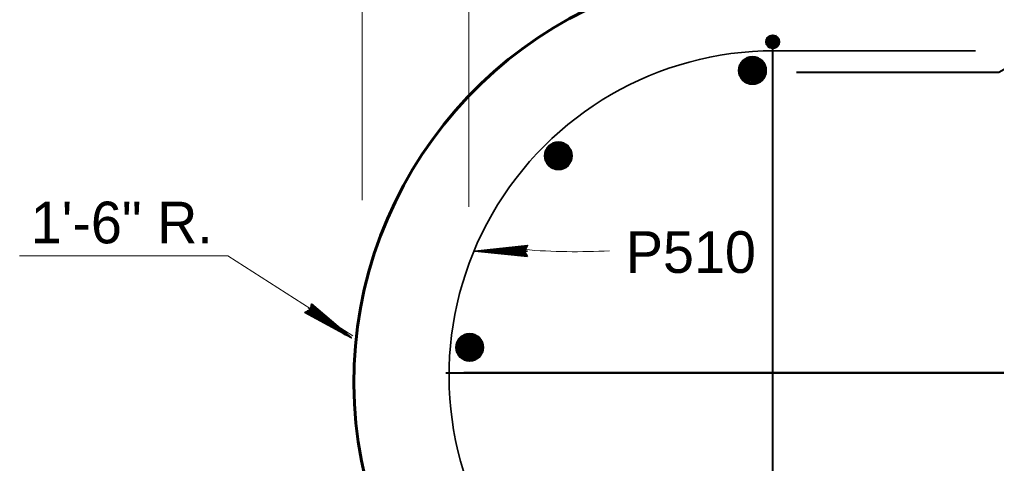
# Model space of a CAD drawing. Extents: x 14.14 to 17.34, y -1.61 to 0.38.
# Drawn here: x 14.4549 to 14.6504, y -0.5088 to -0.42 of the extents above; entities that cross this region are included whole.
import ezdxf

# ---------------------------------------------------------------- set-up
doc = ezdxf.new("R2010")
doc.units = 0
doc.header["$LTSCALE"] = 0.0033
doc.layers.add('1', color=7, linetype='Continuous', lineweight=40)

msp = doc.modelspace()

# ---------------------------------------------------------------- linework, layer by layer
at = {"layer": '1', "lineweight": 13}
for p, q in [((14.5235, -0.456083), (14.5235, -0.32)), ((14.544833, -0.457417), (14.544833, -0.3515))]:
    msp.add_line(p, q, dxfattribs=at)
at = {"layer": '1'}
for p, q in [((14.605, -0.425583), (14.604667, -0.423583)), ((14.605083, -0.4255), (14.60475, -0.423583)), ((14.606333, -0.42325), (14.604833, -0.423333)), ((14.606333, -0.423417), (14.604833, -0.4235)), ((14.606333, -0.4235), (14.604833, -0.423583)), ((14.606333, -0.423583), (14.604833, -0.423667)), ((14.605167, -0.4255), (14.604833, -0.423583)), ((14.606333, -0.423667), (14.604833, -0.42375)), ((14.606333, -0.42375), (14.604833, -0.423833)), ((14.606333, -0.423833), (14.604833, -0.423917)), ((14.606333, -0.423917), (14.604833, -0.424)), ((14.606333, -0.423917), (14.604833, -0.424)), ((14.606333, -0.424), (14.604833, -0.424167)), ((14.606333, -0.424167), (14.604833, -0.424333)), ((14.60525, -0.4255), (14.604917, -0.4235)), ((14.6055, -0.4255), (14.605083, -0.4235)), ((14.605667, -0.425417), (14.60525, -0.4235)), ((14.60575, -0.425417), (14.605333, -0.4235)), ((14.605833, -0.425417), (14.605417, -0.423417)), ((14.605917, -0.425417), (14.605583, -0.423417)), ((14.606, -0.425333), (14.605667, -0.423417)), ((14.606167, -0.425333), (14.60575, -0.423333)), ((14.60625, -0.425333), (14.605833, -0.423333)), ((14.606333, -0.425333), (14.606, -0.423333)), ((14.606417, -0.425333), (14.606083, -0.423333)), ((14.606583, -0.42525), (14.60625, -0.423333)), ((14.606417, -0.424333), (14.604917, -0.424417)), ((14.606417, -0.424417), (14.604917, -0.4245)), ((14.606417, -0.4245), (14.604917, -0.424583)), ((14.606417, -0.424583), (14.604917, -0.424667)), ((14.606417, -0.424667), (14.604917, -0.42475)), ((14.606417, -0.42475), (14.604917, -0.424833)), ((14.606417, -0.424833), (14.604917, -0.424917)), ((14.606417, -0.425), (14.604917, -0.425083)), ((14.606417, -0.425083), (14.604917, -0.425167)), ((14.606417, -0.425167), (14.604917, -0.42525)), ((14.606417, -0.42525), (14.604917, -0.425333)), ((14.606417, -0.425333), (14.604917, -0.425417)), ((14.605583, -0.425833), (14.605583, -0.557167)), ((14.601833, -0.429083), (14.603167, -0.428083)), ((14.603917, -0.428917), (14.602667, -0.42775)), ((14.5995, -0.428583), (14.604083, -0.43075)), ((14.599583, -0.43), (14.603417, -0.43075)), ((14.599667, -0.429583), (14.6035, -0.43025)), ((14.599667, -0.42975), (14.6035, -0.4305)), ((14.59975, -0.429), (14.603667, -0.42975)), ((14.59975, -0.429167), (14.603667, -0.429917)), ((14.59975, -0.429417), (14.603583, -0.430167)), ((14.599833, -0.428583), (14.60375, -0.42925)), ((14.599833, -0.42875), (14.60375, -0.4295)), ((14.599917, -0.42825), (14.60375, -0.428917)), ((14.599333, -0.431333), (14.603167, -0.432083)), ((14.599333, -0.4315), (14.603167, -0.43225)), ((14.599417, -0.430833), (14.603333, -0.431583)), ((14.599417, -0.431), (14.60325, -0.43175)), ((14.599417, -0.43125), (14.60325, -0.431917)), ((14.5995, -0.430417), (14.603417, -0.431167)), ((14.599583, -0.430167), (14.603417, -0.430917)), ((14.603667, -0.43175), (14.599917, -0.432167)), ((14.560667, -0.445667), (14.56525, -0.447833)), ((14.561, -0.445667), (14.564917, -0.446333)), ((14.561083, -0.445333), (14.564917, -0.446)), ((14.563, -0.446167), (14.564333, -0.445167)), ((14.565083, -0.446), (14.563833, -0.444833)), ((14.560667, -0.4475), (14.564583, -0.44825)), ((14.56075, -0.447083), (14.564583, -0.447833)), ((14.56075, -0.44725), (14.564583, -0.448)), ((14.560833, -0.446667), (14.564667, -0.447333)), ((14.560833, -0.446833), (14.564667, -0.447583)), ((14.560917, -0.446083), (14.564833, -0.446833)), ((14.560917, -0.44625), (14.564833, -0.447)), ((14.560917, -0.4465), (14.56475, -0.44725)), ((14.561, -0.445833), (14.564917, -0.446583)), ((14.5605, -0.448417), (14.564333, -0.449167)), ((14.5605, -0.448583), (14.564333, -0.449333)), ((14.560583, -0.447917), (14.5645, -0.448667)), ((14.560583, -0.448083), (14.564417, -0.448833)), ((14.560583, -0.448333), (14.564417, -0.449)), ((14.564833, -0.448833), (14.561083, -0.44925)), ((14.542917, -0.484), (14.5475, -0.486167)), ((14.543167, -0.484417), (14.547083, -0.485167)), ((14.543167, -0.484583), (14.547083, -0.485333)), ((14.543167, -0.484833), (14.547, -0.485583)), ((14.54325, -0.484), (14.547167, -0.484667)), ((14.54325, -0.484167), (14.547167, -0.484917)), ((14.543333, -0.483667), (14.547167, -0.484333)), ((14.54525, -0.4845), (14.546583, -0.4835)), ((14.547333, -0.484333), (14.546083, -0.483167)), ((14.54275, -0.48675), (14.546583, -0.4875)), ((14.542833, -0.48625), (14.54675, -0.487)), ((14.542833, -0.486417), (14.546667, -0.487167)), ((14.542833, -0.486667), (14.546667, -0.487333)), ((14.542917, -0.485833), (14.546833, -0.486583)), ((14.543, -0.485417), (14.546833, -0.486167)), ((14.543, -0.485583), (14.546833, -0.486333)), ((14.543083, -0.485), (14.546917, -0.485667)), ((14.543083, -0.485167), (14.546917, -0.485917)), ((14.54275, -0.486917), (14.546583, -0.487667)), ((14.547083, -0.487167), (14.543333, -0.487583)), ((14.54025, -0.490667), (14.964167, -0.490667))]:
    msp.add_line(p, q, dxfattribs=at)
at = {"layer": '1', "lineweight": 35}
for p, q in [((14.60525, -0.42625), (14.64625, -0.42625)), ((14.556333, -0.46525), (14.549, -0.466083)), ((14.556583, -0.466333), (14.546, -0.466333)), ((14.556333, -0.467167), (14.5485, -0.466167)), ((14.556333, -0.467167), (14.5485, -0.466333)), ((14.556333, -0.467333), (14.5485, -0.466417)), ((14.556333, -0.467333), (14.5485, -0.466417)), ((14.556333, -0.46725), (14.5485, -0.466417)), ((14.556333, -0.465417), (14.549, -0.466167)), ((14.556333, -0.4655), (14.549, -0.466333)), ((14.556417, -0.465667), (14.549083, -0.466417)), ((14.513417, -0.477), (14.519417, -0.482167)), ((14.5135, -0.477), (14.519417, -0.482167)), ((14.5135, -0.477), (14.519417, -0.482167)), ((14.51225, -0.478667), (14.51875, -0.482167)), ((14.512333, -0.4785), (14.518917, -0.482)), ((14.512417, -0.47825), (14.518917, -0.481917)), ((14.512417, -0.478583), (14.518833, -0.482167)), ((14.512667, -0.477583), (14.521333, -0.483667)), ((14.513333, -0.477083), (14.519333, -0.48225)), ((14.513333, -0.477083), (14.519167, -0.482417))]:
    msp.add_line(p, q, dxfattribs=at)
at = {"layer": '1', "lineweight": 60}
for p, q in [((14.59975, -0.428583), (14.599583, -0.4315)), ((14.6, -0.428583), (14.59975, -0.4315)), ((14.600167, -0.428583), (14.6, -0.431583)), ((14.600333, -0.428583), (14.600083, -0.431583)), ((14.6005, -0.428583), (14.600333, -0.431583)), ((14.60075, -0.428583), (14.600583, -0.431583)), ((14.601, -0.428583), (14.60075, -0.431583)), ((14.601083, -0.428667), (14.600917, -0.431583)), ((14.60125, -0.428667), (14.601083, -0.431583)), ((14.601417, -0.428667), (14.60125, -0.431583)), ((14.601667, -0.428667), (14.601417, -0.431583)), ((14.601833, -0.428667), (14.601667, -0.431583)), ((14.602083, -0.42875), (14.601833, -0.431667)), ((14.602333, -0.42875), (14.602083, -0.431667)), ((14.6025, -0.42875), (14.602333, -0.431667)), ((14.602583, -0.42875), (14.602417, -0.431667)), ((14.60275, -0.42875), (14.602583, -0.431667)), ((14.602833, -0.42875), (14.602667, -0.431667)), ((14.603083, -0.428833), (14.602833, -0.43175)), ((14.60325, -0.428833), (14.603083, -0.43175)), ((14.603417, -0.428833), (14.603167, -0.43175)), ((14.603583, -0.428833), (14.603417, -0.43175)), ((14.603833, -0.428833), (14.603667, -0.43175)), ((14.604083, -0.43075), (14.603917, -0.428917)), ((14.604083, -0.43075), (14.599333, -0.4315)), ((14.560917, -0.445667), (14.56075, -0.448583)), ((14.561167, -0.445667), (14.560917, -0.448583)), ((14.561333, -0.445667), (14.561167, -0.448667)), ((14.5615, -0.445667), (14.56125, -0.448667)), ((14.561667, -0.445667), (14.5615, -0.448667)), ((14.561917, -0.445667), (14.56175, -0.448667)), ((14.562167, -0.445667), (14.561917, -0.448667)), ((14.56225, -0.44575), (14.562083, -0.448667)), ((14.562417, -0.44575), (14.56225, -0.448667)), ((14.562583, -0.44575), (14.562417, -0.448667)), ((14.562833, -0.44575), (14.562583, -0.448667)), ((14.563, -0.44575), (14.562833, -0.448667)), ((14.56325, -0.445833), (14.563, -0.44875)), ((14.5635, -0.445833), (14.56325, -0.44875)), ((14.563667, -0.445833), (14.5635, -0.44875)), ((14.56375, -0.445833), (14.563583, -0.44875)), ((14.563917, -0.445833), (14.56375, -0.44875)), ((14.564, -0.445833), (14.563833, -0.44875)), ((14.56425, -0.445917), (14.564, -0.448833)), ((14.564417, -0.445917), (14.56425, -0.448833)), ((14.564583, -0.445917), (14.564333, -0.448833)), ((14.56475, -0.445917), (14.564583, -0.448833)), ((14.565, -0.445917), (14.564833, -0.448833)), ((14.56525, -0.447833), (14.565083, -0.446)), ((14.56525, -0.447833), (14.5605, -0.448583)), ((14.543167, -0.484), (14.543, -0.486917)), ((14.543417, -0.484), (14.543167, -0.486917)), ((14.543583, -0.484), (14.543417, -0.487)), ((14.54375, -0.484), (14.5435, -0.487)), ((14.543917, -0.484), (14.54375, -0.487)), ((14.544167, -0.484), (14.544, -0.487)), ((14.544417, -0.484), (14.544167, -0.487)), ((14.5445, -0.484083), (14.544333, -0.487)), ((14.544667, -0.484083), (14.5445, -0.487)), ((14.544833, -0.484083), (14.544667, -0.487)), ((14.545083, -0.484083), (14.544833, -0.487)), ((14.54525, -0.484083), (14.545083, -0.487)), ((14.5455, -0.484167), (14.54525, -0.487083)), ((14.54575, -0.484167), (14.5455, -0.487083)), ((14.545917, -0.484167), (14.54575, -0.487083)), ((14.546, -0.484167), (14.545833, -0.487083)), ((14.546167, -0.484167), (14.546, -0.487083)), ((14.54625, -0.484167), (14.546083, -0.487083)), ((14.5465, -0.48425), (14.54625, -0.487167)), ((14.546667, -0.48425), (14.5465, -0.487167)), ((14.546833, -0.48425), (14.546583, -0.487167)), ((14.547, -0.48425), (14.546833, -0.487167)), ((14.54725, -0.48425), (14.547083, -0.487167)), ((14.5475, -0.486167), (14.547333, -0.484333)), ((14.5475, -0.486167), (14.54275, -0.486917))]:
    msp.add_line(p, q, dxfattribs=at)
at = {"layer": '1'}
for points in [[(14.605583, -0.42575), (14.605917, -0.423167), (14.606417, -0.4255), (14.605333, -0.423167), (14.604917, -0.425583), (14.604583, -0.423583), (14.606667, -0.423583), (14.604333, -0.4245), (14.606917, -0.42425), (14.604583, -0.42525), (14.606917, -0.424917), (14.604333, -0.424083), (14.606083, -0.425667), (14.60625, -0.42325), (14.604417, -0.424917), (14.606833, -0.423833), (14.606417, -0.4255), (14.604917, -0.425583), (14.604333, -0.4245), (14.604583, -0.423583), (14.605333, -0.423167), (14.60625, -0.42325), (14.606833, -0.423833), (14.60575, -0.4245), (14.604833, -0.423333), (14.604583, -0.42525), (14.60575, -0.4245), (14.60625, -0.425583), (14.606917, -0.424583), (14.605833, -0.4245), (14.604583, -0.423667), (14.605833, -0.425667), (14.606167, -0.424333), (14.606667, -0.423583)], [(14.610417, -0.4305), (14.650917, -0.4305), (14.658167, -0.426333), (14.888, -0.426333)], [(14.599333, -0.4315), (14.601417, -0.43275), (14.603167, -0.43225), (14.604083, -0.43075)], [(14.5605, -0.448583), (14.562583, -0.449833), (14.564333, -0.449333), (14.56525, -0.447833)], [(14.54275, -0.486917), (14.544833, -0.488167), (14.546583, -0.487667), (14.5475, -0.486167)], [(14.74375, -0.490667), (14.665167, -0.490667), (14.543833, -0.490667)]]:
    msp.add_lwpolyline(points, dxfattribs=at)
at = {"layer": '1', "lineweight": 60}
for points in [[(14.603167, -0.43225), (14.603167, -0.428083), (14.6015, -0.43275), (14.602, -0.427583), (14.599917, -0.432167), (14.600667, -0.427667), (14.60225, -0.432667), (14.599083, -0.429333), (14.603917, -0.428917), (14.600667, -0.432583), (14.602667, -0.42775), (14.5995, -0.428583), (14.599333, -0.4315)], [(14.599917, -0.432167), (14.601417, -0.429917), (14.59925, -0.429), (14.60125, -0.427583), (14.601417, -0.429833), (14.603083, -0.432167), (14.599083, -0.429833), (14.601833, -0.429083)], [(14.602667, -0.42775), (14.601417, -0.429917), (14.603667, -0.43175)], [(14.598917, -0.43025), (14.604083, -0.429583), (14.5995, -0.428583)], [(14.560083, -0.447333), (14.56525, -0.446667), (14.560667, -0.445667)], [(14.564333, -0.449333), (14.564333, -0.445167), (14.562667, -0.449833), (14.563167, -0.444667), (14.561083, -0.44925), (14.561833, -0.44475), (14.563417, -0.44975), (14.56025, -0.446417), (14.565083, -0.446), (14.561833, -0.449667), (14.563833, -0.444833), (14.560667, -0.445667), (14.5605, -0.448583)], [(14.561083, -0.44925), (14.562583, -0.447), (14.560417, -0.446083), (14.562417, -0.444667), (14.562583, -0.446917), (14.56425, -0.44925), (14.56025, -0.446917), (14.563, -0.446167)], [(14.563833, -0.444833), (14.562583, -0.447), (14.564833, -0.448833)], [(14.542333, -0.485667), (14.5475, -0.485), (14.542917, -0.484)], [(14.546583, -0.487667), (14.546583, -0.4835), (14.544917, -0.488167), (14.545417, -0.483), (14.543333, -0.487583), (14.544083, -0.483083), (14.545667, -0.488083), (14.5425, -0.48475), (14.547333, -0.484333), (14.544083, -0.488), (14.546083, -0.483167), (14.542917, -0.484), (14.54275, -0.486917)], [(14.543333, -0.487583), (14.544833, -0.485333), (14.542667, -0.484417), (14.544667, -0.483), (14.544833, -0.48525), (14.5465, -0.487583), (14.5425, -0.48525), (14.54525, -0.4845)], [(14.546083, -0.483167), (14.544833, -0.485333), (14.547083, -0.487167)]]:
    msp.add_lwpolyline(points, dxfattribs=at)
at = {"layer": '1', "lineweight": 35}
for points in [[(14.556583, -0.467417), (14.546, -0.466333), (14.556583, -0.465167), (14.556, -0.466333)], [(14.555833, -0.466417), (14.551167, -0.4665), (14.551167, -0.466417), (14.552083, -0.466417), (14.555833, -0.4665), (14.552833, -0.466583), (14.556, -0.466667), (14.55375, -0.46675), (14.556, -0.466833), (14.5525, -0.466583), (14.547833, -0.466417), (14.54875, -0.466167), (14.5475, -0.466167), (14.555833, -0.466167), (14.553417, -0.466), (14.556, -0.466), (14.550667, -0.466417), (14.556, -0.46575)], [(14.513333, -0.476833), (14.521333, -0.483667), (14.512, -0.478583), (14.513167, -0.478)], [(14.513333, -0.478083), (14.51725, -0.480667), (14.517167, -0.480667), (14.516417, -0.480167), (14.513417, -0.477917), (14.515917, -0.479583), (14.513417, -0.477667), (14.51525, -0.479), (14.5135, -0.477583), (14.516167, -0.479833), (14.519917, -0.482667), (14.519, -0.482333), (14.520083, -0.483083), (14.513167, -0.47825), (14.515083, -0.47975), (14.512917, -0.47825), (14.517583, -0.481), (14.51275, -0.478417)]]:
    msp.add_lwpolyline(points, close=True, dxfattribs=at)
for points in [[(14.555833, -0.466417), (14.55625, -0.467167), (14.556, -0.466917), (14.555833, -0.466583), (14.555583, -0.466667), (14.55575, -0.467), (14.555917, -0.46625), (14.556083, -0.46575), (14.556333, -0.465333)], [(14.513333, -0.478083), (14.513417, -0.477167), (14.5135, -0.4775), (14.5135, -0.477833), (14.51375, -0.477917), (14.51375, -0.4775), (14.513167, -0.478083), (14.51275, -0.478333), (14.512333, -0.478667)]]:
    msp.add_lwpolyline(points, dxfattribs=at)
at = {"layer": '1', "lineweight": 13}
msp.add_lwpolyline([(14.454917, -0.46725), (14.496583, -0.46725), (14.521583, -0.48325)], dxfattribs=at)
at = {"layer": '1'}
msp.add_circle((14.605633, -0.424417), 0.00132, dxfattribs=at)
at = {"layer": '1', "lineweight": 60}
for centre in [(14.601583, -0.43015), (14.56275, -0.447233), (14.545, -0.485567)]:
    msp.add_circle(centre, 0.00264, dxfattribs=at)
msp.add_arc((14.604667, -0.4925), 0.082833, 97.64809, 263.01663, dxfattribs=at)
at = {"layer": '1', "lineweight": 35}
msp.add_arc((14.605917, -0.49125), 0.065042, 90, 270.57654, dxfattribs=at)
at = {"layer": '1', "lineweight": 13}
msp.add_arc((14.56633, -0.338196), 0.128228, 265.34169, 272.98148, dxfattribs=at)

# ---------------------------------------------------------------- texts
at = {"layer": '1'}
for s, p in [('1\'-6" R.', (14.457167, -0.46475)), ('P510', (14.57625, -0.470667))]:
    msp.add_text(s, height=0.008334, dxfattribs=at).set_placement(p)

doc.saveas('drawing.dxf')
